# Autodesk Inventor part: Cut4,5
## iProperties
Created: 2010-10
Part Number: Cut4,5
Document SubType Name: Modeling
Designer: Administrator
Density: 1.4 g/cm^3
Material: PVC-U
Mass: 379.719 g
Surface Area: 342.403 cm^2
Volume: 271.228 cm^3
Author: Administrator
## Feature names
1. Base1
